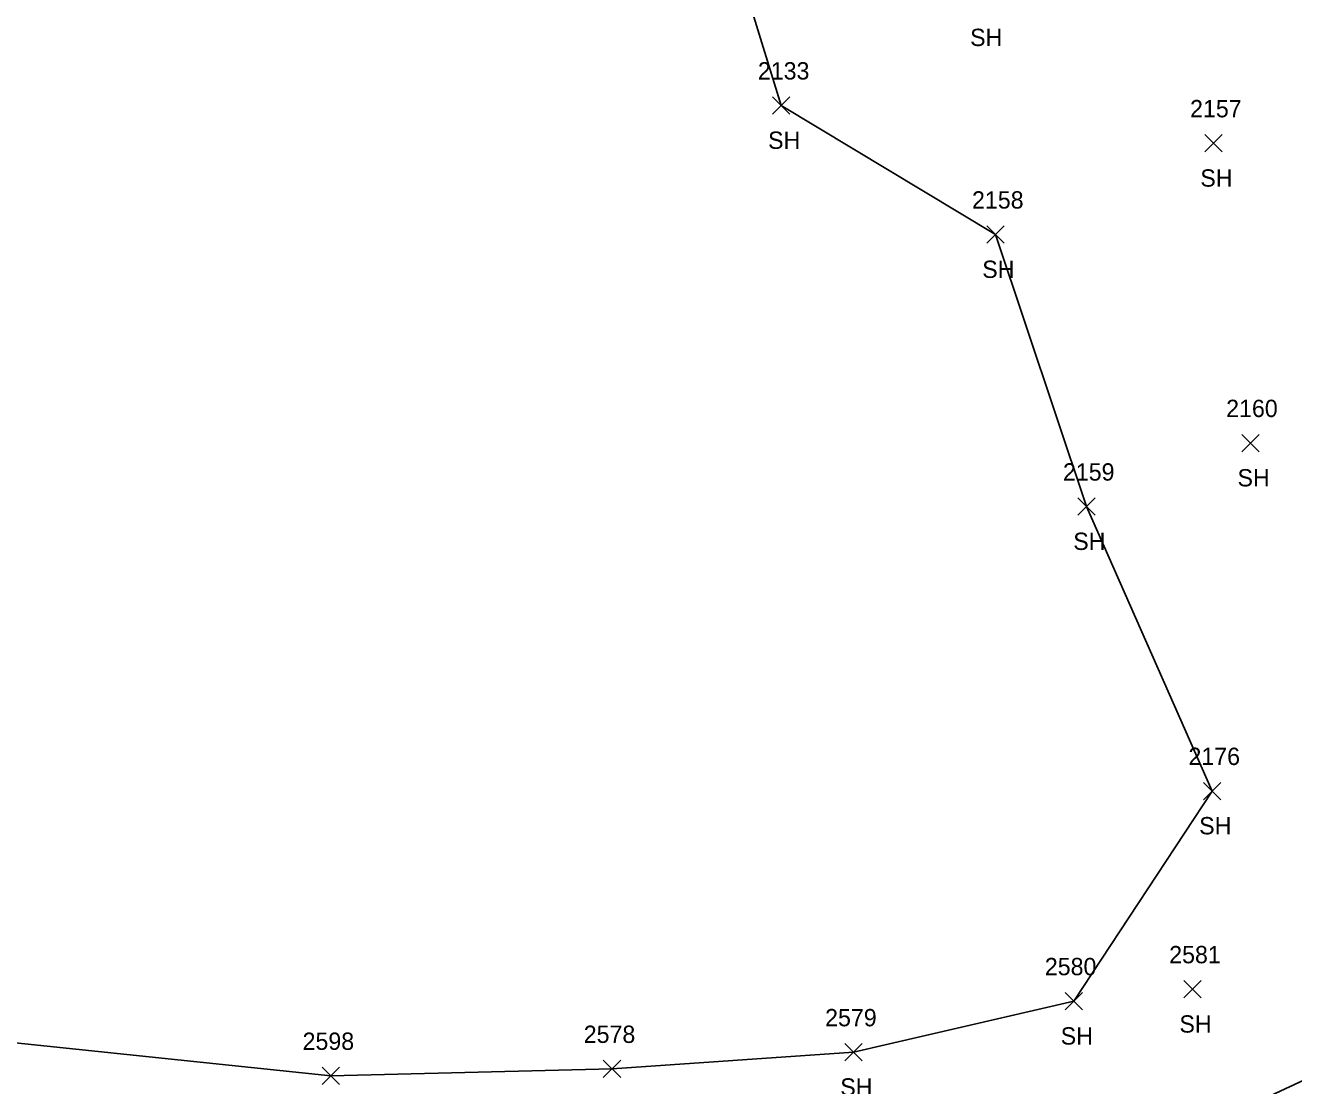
# Model space of a CAD drawing. Extents: x 1443590 to 1445966, y 578314 to 580556.
# Drawn here: x 1444767.8 to 1444914.1, y 579213.2 to 579335.5 of the extents above; entities that cross this region are included whole.
import ezdxf

# ---------------------------------------------------------------- set-up
doc = ezdxf.new("R2010")
doc.units = 0
for name, color, linetype in [('L_A', 7, 'Continuous'), ('L_I', 7, 'Continuous'), ('L_TIC', 7, 'Continuous'), ('LELB', 7, 'Continuous'), ('LSOGP', 7, 'Continuous')]:
    doc.layers.add(name, color=color, linetype=linetype)

msp = doc.modelspace()

# ---------------------------------------------------------------- linework, layer by layer
at = {"layer": 'L_TIC'}
for points in [[(1444853.99, 579325.22), (1444855.99, 579327.22)], [(1444855.99, 579325.22), (1444853.99, 579327.22)], [(1444903.86, 579320.86), (1444905.86, 579322.86)], [(1444905.86, 579320.86), (1444903.86, 579322.86)], [(1444878.7, 579310.33), (1444880.7, 579312.33)], [(1444880.7, 579310.33), (1444878.7, 579312.33)], [(1444908.15, 579286.28), (1444910.15, 579288.28)], [(1444910.15, 579286.28), (1444908.15, 579288.28)], [(1444889.2, 579278.95), (1444891.2, 579280.95)], [(1444891.2, 579278.95), (1444889.2, 579280.95)], [(1444903.73, 579246.14), (1444905.73, 579248.14)], [(1444905.73, 579246.14), (1444903.73, 579248.14)], [(1444901.45, 579223.27), (1444903.45, 579225.27)], [(1444903.45, 579223.27), (1444901.45, 579225.27)], [(1444887.75, 579221.89), (1444889.75, 579223.89)], [(1444889.75, 579221.89), (1444887.75, 579223.89)], [(1444862.32, 579216), (1444864.32, 579218)], [(1444864.32, 579216), (1444862.32, 579218)], [(1444834.47, 579214.08), (1444836.47, 579216.08)], [(1444836.47, 579214.08), (1444834.47, 579216.08)], [(1444802.03, 579213.28), (1444804.03, 579215.28)], [(1444804.03, 579213.28), (1444802.03, 579215.28)]]:
    msp.add_lwpolyline(points, dxfattribs=at)
at = {"layer": 'LELB'}
msp.add_lwpolyline([(1444919.24, 579215.63), (1444903.05, 579208.11), (1444885.02, 579194.5), (1444865.75, 579185.31), (1444848.32, 579178.64), (1444837.14, 579166.25), (1444806.08, 579168.28), (1444761.27, 579170.06), (1444728.49, 579174.89), (1444695.59, 579190.16), (1444696.54, 579181.03), (1444600.23, 579193.23), (1444579.91, 579197.07)], dxfattribs=at)
at = {"layer": 'LSOGP'}
msp.add_lwpolyline([(1444847.54, 579350.44), (1444854.99, 579326.23), (1444879.7, 579311.33), (1444890.2, 579279.95), (1444904.73, 579247.14), (1444888.76, 579222.89), (1444863.33, 579217), (1444835.47, 579215.08), (1444803.04, 579214.28), (1444764.36, 579218.34), (1444726.72, 579227.69), (1444697.07, 579233.22), (1444650.35, 579264.33), (1444623.43, 579260.54), (1444602.77, 579253.51), (1444571.76, 579243.16), (1444548.12, 579235.92)], dxfattribs=at)

# ---------------------------------------------------------------- texts
at = {"layer": 'L_A'}
for p in [(1444876.79, 579333.08), (1444853.48, 579321.22), (1444903.35, 579316.86), (1444878.19, 579306.33), (1444907.64, 579282.28), (1444888.69, 579274.95), (1444903.22, 579242.14), (1444900.94, 579219.27), (1444887.24, 579217.89), (1444861.81, 579212)]:
    msp.add_text('SH', height=2, dxfattribs=at).set_placement(p)
at = {"layer": 'L_I'}
for s, p in [('2133', (1444852.3, 579329.22)), ('2157', (1444902.17, 579324.86)), ('2158', (1444877.01, 579314.33)), ('2160', (1444906.33, 579290.28)), ('2159', (1444887.5, 579282.95)), ('2176', (1444901.98, 579250.14)), ('2581', (1444899.76, 579227.27)), ('2580', (1444885.41, 579225.89)), ('2579', (1444860.06, 579220)), ('2598', (1444799.77, 579217.28)), ('2578', (1444832.21, 579218.08))]:
    msp.add_text(s, height=2, dxfattribs=at).set_placement(p)

doc.saveas('drawing.dxf')
